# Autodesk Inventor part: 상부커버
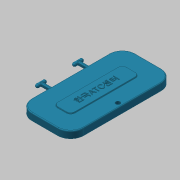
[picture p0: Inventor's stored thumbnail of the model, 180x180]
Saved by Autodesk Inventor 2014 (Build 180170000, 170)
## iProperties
Created: 2016-02
Part Number: 상부커버
Material: ABS 플라스틱
Document SubType Name: Modeling
Designer: mduedu
Density: 1.06 g/cm^3
Mass: 61.4476 g
Surface Area: 174.433 cm^2
Volume: 57.9694 cm^3
Appearance: Turquoise
Author: mduedu
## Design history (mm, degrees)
sketch "스케치1"
  geometry: L1 (30, 60)-(-30, 60); L2 (-30, 60)-(-30, -60); L3 (-30, -60)-(30, -60); L4 (30, -60)-(30, 60); L5 (30, 60)-(-30, -60); L6 (-30, 60)-(30, -60); 1 further point
  constraints: 12 end point, 2 midpoint, 2 parallel, 1 horizontal, 1 perpendicular
  dimensions: "d0" = 60 distance of L2.end L3.end; "d2" = 120 distance of L1.end L2.end
extrude "돌출1" new body sketch "스케치1" distance "d3" = 8; taper "d4" = 0 deg
fillet "모깎기1" dims "d5" = 15
node "작업 평면1"
sketch "스케치7"
  geometry: L1 (-39, 4)-(129, 4) reference; L2 (65, 2)-(68, 2); L3 (68, 2)-(68, 6); L4 (68, 6)-(65, 6); L5 (65, 6)-(65, 2); L6 (65, 2)-(68, 6); L7 (68, 2)-(65, 6); 2 further points
  constraints: 12 end point, 2 midpoint, 2 parallel, 1 horizontal, 1 perpendicular, 1 point on line
  dimensions: "d33" = 4 distance of L2.end L3.end; "d35" = 3 distance of L3.end L4.end; "d36" = 20 distance from line of L5 point (45, 0)
extrude "돌출3" join sketch "스케치7" distance "d37" = 15; taper "d38" = 0 deg
fillet "모깎기6" dims "d39" = 2
node "작업 평면3"
sketch "스케치8"
  geometry: A1 r 2 centre (-13, 2) between (-13, 4) and (-13, 0) reference; 2 further points
  constraints: 1 coincident, 1 vertical alignment, 2 other
extrude "돌출4" join sketch "스케치8" stored distance "d40" = 12; taper "d41" = 0 deg
fillet "모깎기7" dims "d42" = 2
fillet "모깎기8" dims "d43" = 1
fillet "모깎기9" dims "d44" = 1
sketch "스케치2"
  geometry: L1 (30, 45)-(30, -45) reference; L2 (15, -60)-(-15, -60) reference; L3 (-30, -45)-(-30, 45) reference; L4 (-15, 60)-(15, 60) reference; L5 (25, 45)-(25, -45); L6 (15, -55)-(-15, -55); L7 (-25, -45)-(-25, 45); L8 (-15, 55)-(15, 55); A1 r 15 centre (15, 45) between (30, 45) and (15, 60) reference; A2 r 15 centre (15, -45) between (15, -60) and (30, -45) reference; A3 r 15 centre (-15, -45) between (-30, -45) and (-15, -60) reference; A4 r 15 centre (-15, 45) between (-15, 60) and (-30, 45) reference; A5 r 10 centre (15, 45) between (25, 45) and (15, 55); A6 r 10 centre (15, -45) between (15, -55) and (25, -45); A7 r 10 centre (-15, -45) between (-25, -45) and (-15, -55); A8 r 10 centre (-15, 45) between (-15, 55) and (-25, 45); 4 further points
  constraints: 8 end point, 8 point on circle, 4 centre point, 4 midpoint, 7 other
  dimensions: "d8" = 5 distance between parallel lines of L7 L3
hole "구멍1" sketch "스케치2" at (25, 0) diameter "d9" = 5; stored, may be unused: countersink angle "d13" = 90 deg, drill point angle "d15" = 118 deg; dims "d10" = 6, "d11" = 4, "d12" = 2, "d14" = 8
sketch "스케치3"
  geometry: L1 (10, -40)-(-10, -40); L2 (-10, -40)-(-10, 40); L3 (-10, 40)-(10, 40); L4 (10, 40)-(10, -40); L5 (10, -40)-(-10, 40); L6 (-10, -40)-(10, 40); 1 further point
  constraints: 12 end point, 2 midpoint, 2 parallel, 1 horizontal, 1 perpendicular
  dimensions: "d16" = 80 distance of L1.end L2.end; "d18" = 20 distance of L2.end L3.end
extrude "돌출2" join sketch "스케치3" distance "d19" = 1; taper "d20" = 0 deg
fillet "모깎기2" dims "d21" = 5
fillet "모깎기3" dims "d22" = 0.3
sketch "스케치4"
  geometry: 2 further points
  constraints: 1 coincident, 1 other
feature "엠보싱1" sketch "스케치4" dims "d8" = 5, "d24" = 0.5, "d25" = 0
fillet "모깎기10" dims "d45" = 1
node "솔리드1"
mirror "대칭1"
node "절단 모서리 투영1"
